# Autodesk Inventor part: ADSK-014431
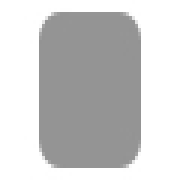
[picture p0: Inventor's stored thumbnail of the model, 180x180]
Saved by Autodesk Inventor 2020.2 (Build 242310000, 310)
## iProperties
IsCustomPart: 1
Created: 2019-01
Part Number: ADSK-014431
Material: Stahl, weich
Document SubType Name: Modeling
Designer: lutzd
Language: de-DE
Size Designation: 5 x 40 x 40
Categories: <MemberInstance><Categories><Category DisplayName="Sonstige Bauteile" InternalName="5aa15e00-363f-49f2-933f-16f664388e3f" Mnemonic="OTHER"><Category DisplayName
Mass: 61.9577 g
Surface Area: 39.1416 cm^2
Volume: 7.8927 cm^3
Density: 7.85 g/cm^3
Appearance: Semi-Polished(8)
DocNumber: ADSK-014431
Folder: 01 - Themengebiete\Simplification\01 - Packaging machine\
VDS_Category: 3D Komponenten
VDS_NumSchm: Autodesk
Dimensions: 40x5x40 mm
Mass: 0,062 kg
VLT_Material: Stahl, weich
Title: end cap
Author: lutzd
Revision Number: -
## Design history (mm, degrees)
sketch "Sketch1"
  geometry: L1 (0, 20.175)-(0, -21.446); L2 (-20.203, 0)-(20.169, 0); L3 (-20, 20)-(20, 20); L4 (20, 20)-(20, -20); L5 (20, -20)-(-20, -20); L6 (-20, -20)-(-20, 20); 1 further point
  constraints: 12 end point, 2 horizontal, 2 parallel, 2 point on line, 1 perpendicular, 1 vertical
  dimensions: "d0" = 40 distance between parallel lines of L5 L3 (= height); "d1" = 20 distance between parallel lines of L2 L3 (= 0.5 x height); "d2" = 40 distance between parallel lines of L6 L4 (= width); "d3" = 20 distance between parallel lines of L6 L1 (= 0.5 x width)
extrude "Extrusion1" new body sketch "Sketch1" distance "d4" = 5 (= thickness); taper "d5" = 0 deg
fillet "Fillet1" dims "d6" = 5 (= fillet), "d7" = 0, "fillet" = 5 [user parameter; used in 1 equation term]
chamfer "Chamfer1" distance "d8" = 0 (computed from chamfer); stored, may be unused: second distance "d9" = 2, angle "d10" = 45 deg; dims "d11" = 0, "chamfer" = 0 [user parameter; used in 1 equation term]
body "Solid1"
other parameters: "thickness" = 5 [user parameter; used in 1 equation term], "width" = 40 [user parameter; used in 2 equation terms], "height" = 40 [user parameter; used in 2 equation terms]
